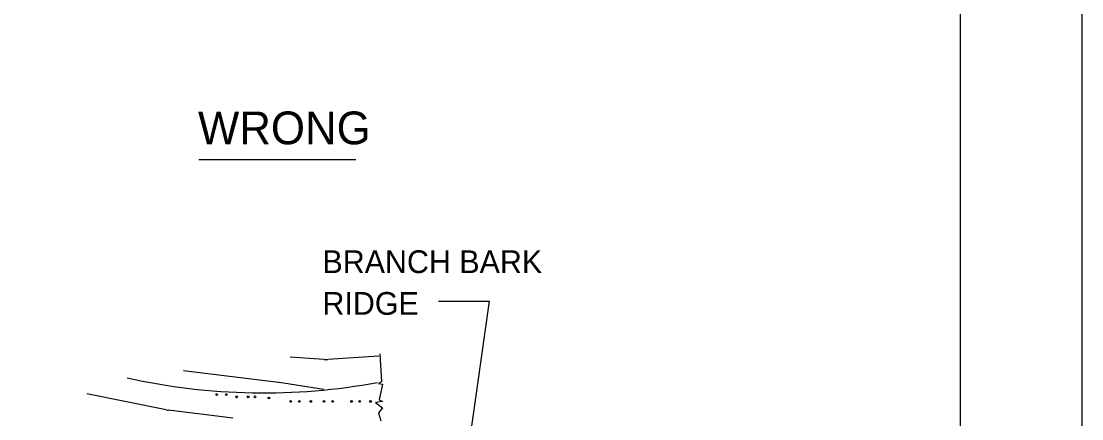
# Model space of a CAD drawing. Extents: x 639115 to 640019, y 298285 to 298879.
# Drawn here: x 639816.1 to 639956, y 298648.2 to 298700.6 of the extents above; entities that cross this region are included whole.
import ezdxf

# ---------------------------------------------------------------- set-up
doc = ezdxf.new("R2010")
doc.units = 0
doc.layers.add('1', color=7, linetype='Continuous')
doc.layers.add('PLT-BNDY', color=7, linetype='Continuous')

msp = doc.modelspace()

# ---------------------------------------------------------------- linework, layer by layer
at = {"layer": '1'}
for p, q in [((639860.29, 298682.34), (639839.56, 298682.34)), ((639871.19, 298663.7), (639877.88, 298663.7)), ((639877.88, 298663.7), (639873.44, 298632.24)), ((639856.08, 298656.02), (639851.64, 298656.31)), ((639863.31, 298656.46), (639856.6, 298656.02)), ((639850.06, 298652.98), (639837.55, 298654.49)), ((639856.04, 298652.06), (639850.19, 298652.96)), ((639835.28, 298649.37), (639824.82, 298651.46)), ((639844.06, 298648.28), (639835.58, 298649.32))]:
    msp.add_line(p, q, dxfattribs=at)
for points in [[(639940.03, 298300.23), (639940.03, 298864.23), (639154.03, 298864.23), (639154.03, 298300.23), (639940.03, 298300.23), (639940.03, 298326.59), (639740.03, 298326.59), (639740.03, 298391.26), (639940.03, 298391.26), (639940.03, 298420.23), (639740.03, 298420.23), (639740.03, 298300.23), (639818.83, 298300.23), (639818.83, 298326.59), (639818.83, 298300.23), (639895.83, 298300.23), (639895.83, 298326.59), (639895.83, 298314.27), (639940.03, 298314.27)], [(639863.46, 298656.76), (639863.65, 298653.05), (639863.27, 298652.82), (639863.8, 298652.75), (639863.35, 298650.7), (639863.8, 298650.47), (639862.89, 298650.32), (639863.8, 298649.64), (639863.27, 298648.96), (639863.57, 298647.9)]]:
    msp.add_lwpolyline(points, dxfattribs=at)
for centre in [(639841.92, 298651.38), (639843.2, 298651.38), (639844.57, 298651.08), (639846.08, 298651.08), (639846.99, 298651.08), (639848.81, 298650.93), (639851.69, 298650.47), (639852.83, 298650.47), (639854.34, 298650.47), (639856.08, 298650.47), (639857.22, 298650.47), (639859.72, 298650.47), (639860.78, 298650.47), (639862.22, 298650.47)]:
    msp.add_circle(centre, 0.111, dxfattribs=at)
for centre, radius, start, end in [((639856.34, 298660.01), 4, 266.3086, 273.7314), ((639848.13, 298734.43), 82.83, 257.4451, 280.4525), ((639849.58, 298649.01), 4, 81.2538, 83.13), ((639836.06, 298653.29), 4, 258.6901, 262.9987)]:
    msp.add_arc(centre, radius, start, end, dxfattribs=at)
at = {"layer": 'PLT-BNDY'}
msp.add_lwpolyline([(639115.03, 298879.23), (639956.03, 298879.23), (639956.03, 298285.23), (639115.03, 298285.23)], close=True, dxfattribs=at)

# ---------------------------------------------------------------- texts
at = {"layer": '1'}
for s, height, p in [('WRONG', 4.32, (639839.46, 298684.38)), ('BRANCH BARK', 2.9997, (639855.88, 298667.4)), ('RIDGE', 3, (639855.88, 298661.9))]:
    msp.add_text(s, height=height, dxfattribs=at).set_placement(p)

doc.saveas('drawing.dxf')
